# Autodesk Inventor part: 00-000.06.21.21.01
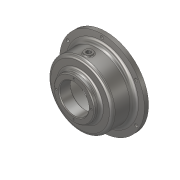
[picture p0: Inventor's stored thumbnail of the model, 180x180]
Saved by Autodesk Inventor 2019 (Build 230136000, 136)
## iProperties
Created: 2019-01
Part Number: 00-000.06.21.21.01
Material: Steel, Mild
Document SubType Name: Modeling
Designer: m.vorobev
Density: 7.85 g/cm^3
Appearance: Semi-Polished
Author: m.vorobev
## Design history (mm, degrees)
sketch "Sketch1"
  geometry: L1 (145, 0)-(100, 0); L2 (100, 0)-(100, 14); L3 (100, 14)-(145, 14); L4 (145, 14)-(145, 0); L5 (100, 14)-(110, 14); L6 (110, 14)-(110, 41); L7 (110, 41)-(100, 41); L8 (100, 41)-(100, 14); L9 (110, 41)-(100, 41); L10 (100, 41)-(100, 89); L11 (100, 89)-(110, 89); L12 (110, 89)-(110, 41); L13 (100, 89)-(70, 89); L14 (70, 89)-(70, 71); L15 (70, 71)-(100, 71); L16 (100, 71)-(100, 89); L17 (50, 70)-(70, 70); L18 (70, 70)-(70, 110); L19 (70, 110)-(50, 110); L20 (50, 110)-(50, 70); L21 (0, 0)-(19.228, 0); L22 (0, 36.823)-(0, 0); L23 (100, 0)-(125, 0); L24 (125, 0)-(125, 4); L25 (125, 4)-(100, 4); L26 (100, 4)-(100, 0); 1 further point
  constraints: 52 end point, 12 parallel, 7 horizontal, 6 perpendicular, 2 collinear, 1 horizontal alignment, 1 midpoint
  dimensions: "d0" = 290 diameter of L4 L22; "d1" = 220 diameter of L12 L22; "d2" = 140 diameter of L18 L22; "d3" = 200 diameter of L10 L22; "d4" = 14 distance of L3.end L1.start; "d5" = 75 distance between parallel lines of L13 L3; "d6" = 18 distance of L13.end L14.end; "d7" = 40 distance of L19.end L17.start; "d8" = 100 diameter of L20 L22; "d9" = 110 distance between parallel lines of L1 L19; "d11" = 4 distance of L23.end L24.end; "d12" = 250 diameter of L24.end L22
revolve "Revolution1" sketch "Sketch1" stored, may be unused: angle "d16" = 90 deg
fillet "Fillet1" dims "d17" = 10, "d18" = 15, "d19" = 3
chamfer "Chamfer1" distance "d20" = 3; stored, may be unused: second distance "d21" = 2, angle "d22" = 45 deg
chamfer "Chamfer2" distance "d23" = 2.5; stored, may be unused: second distance "d24" = 2, angle "d25" = 45 deg
sketch "Sketch2"
  geometry: L1 (43.589, 90)-(-43.589, 90); L2 (-43.589, 90)-(-43.589, 101.006); L3 (-43.589, 101.006)-(43.589, 101.006); L4 (43.589, 101.006)-(43.589, 90); A1 r 100 centre (0, 0) between (43.589, 90) and (-43.589, 90) reference; 1 further point
  constraints: 8 end point, 2 parallel, 2 point on circle, 1 horizontal, 1 perpendicular
  dimensions: "d27" = 90 distance from line of point (0, 0) L1
extrude "Extrusion1" join sketch "Sketch2" distance "d28" = 22; taper "d29" = 0 deg
sketch "Sketch3"
  geometry: L1 (0, 0)-(87.178, 0) reference; 2 further points
  constraints: 1 midpoint
hole "Hole1" sketch "Sketch3" at (43.589, 0) diameter "d30" = 20; stored, may be unused: countersink angle "d34" = 90 deg, drill point angle "d36" = 118 deg; dims "d31" = 6, "d32" = 4, "d33" = 2, "d35" = 25
chamfer "Chamfer3" distance "d37" = 1; stored, may be unused: second distance "d38" = 2, angle "d39" = 45 deg
pattern_circular "Circular Pattern1" dims angle "d41" = 360 deg
sketch "Sketch4"
  geometry: L1 (104.836, 60)-(115, 60); L2 (115, 60)-(115, 46); L3 (115, 46)-(104.836, 46); L4 (104.836, 46)-(104.836, 60); L5 (125, 0)-(-125, 0) reference; 1 further point
  constraints: 8 end point, 2 parallel, 1 horizontal, 1 perpendicular
  dimensions: "d43" = 60 distance from line of L5 L1.end; "d44" = 28 diameter of L3 L1; "d45" = 115 distance from line of point (0, 0) L2
revolve "Revolution2" sketch "Sketch4" stored, may be unused: angle "d46" = 90 deg
sketch "Sketch5"
  geometry: C1 r 14 at (0, 0) reference; 2 further points
  constraints: 1 coincident
hole "Hole2" sketch "Sketch5" at (0, 0) diameter "d47" = 13.835; stored, may be unused: countersink angle "d51" = 90 deg, drill point angle "d53" = 118 deg; dims "d48" = 32, "d49" = 16, "d50" = 2, "d52" = 41.3
fillet "Fillet2" dims "d54" = 3
pattern_circular "Circular Pattern2" dims angle "d56" = 360 deg
sketch "Sketch6"
  geometry: L1 (0, 0)-(0, -60)
  constraints: 2 end point, 1 vertical
  dimensions: "d58" = 60 distance of L1.start L1.end
hole "Hole3" sketch "Sketch6" at (0, -60) diameter "d59" = 6.647; stored, may be unused: countersink angle "d63" = 90 deg, drill point angle "d65" = 118 deg; dims "d60" = 59.25, "d61" = 16, "d62" = 2, "d64" = 100.7
pattern_circular "Circular Pattern3" dims angle "d67" = 360 deg
sketch "Sketch7"
  geometry: L1 (0, 0)-(0, 135)
  constraints: 2 end point, 1 vertical
  dimensions: "d69" = 135 distance of L1.start L1.end
hole "Hole4" sketch "Sketch7" at (0, 135) diameter "d70" = 11; stored, may be unused: countersink angle "d74" = 90 deg, drill point angle "d76" = 118 deg; dims "d71" = 59.25, "d72" = 16, "d73" = 2, "d75" = 100.7
pattern_circular "Circular Pattern4" dims angle "d78" = 360 deg
sketch "Sketch8"
  geometry: L1 (87.178, 0)-(-5.485, 0); L2 (-5.485, 0)-(-5.485, -67.713); L3 (-5.485, -67.713)-(87.178, -67.713); L4 (87.178, -67.713)-(87.178, 0); C1 r 25 at (43.589, -26); 1 further point
  constraints: 8 end point, 2 parallel, 1 centre point, 1 coincident, 1 horizontal, 1 perpendicular
  dimensions: "d80" = 50 diameter of C1
extrude "Extrusion2" cut sketch "Sketch8" stored distance "d81" = 20; taper "d82" = 0 deg; dims "d0" = 290, "d1" = 220, "d2" = 140, "d3" = 200, "d4" = 14, "d5" = 75, "d6" = 18, "d7" = 40, "d8" = 100, "d9" = 110, "d11" = 4, "d12" = 250
pattern_circular "Circular Pattern5" dims angle "d84" = 360 deg
delete_face "Delete Face1"
delete_face "Delete Face2"
delete_face "Delete Face3"
delete_face "Delete Face4"
fillet "Fillet3" dims "d86" = 3
body "Solid1"
